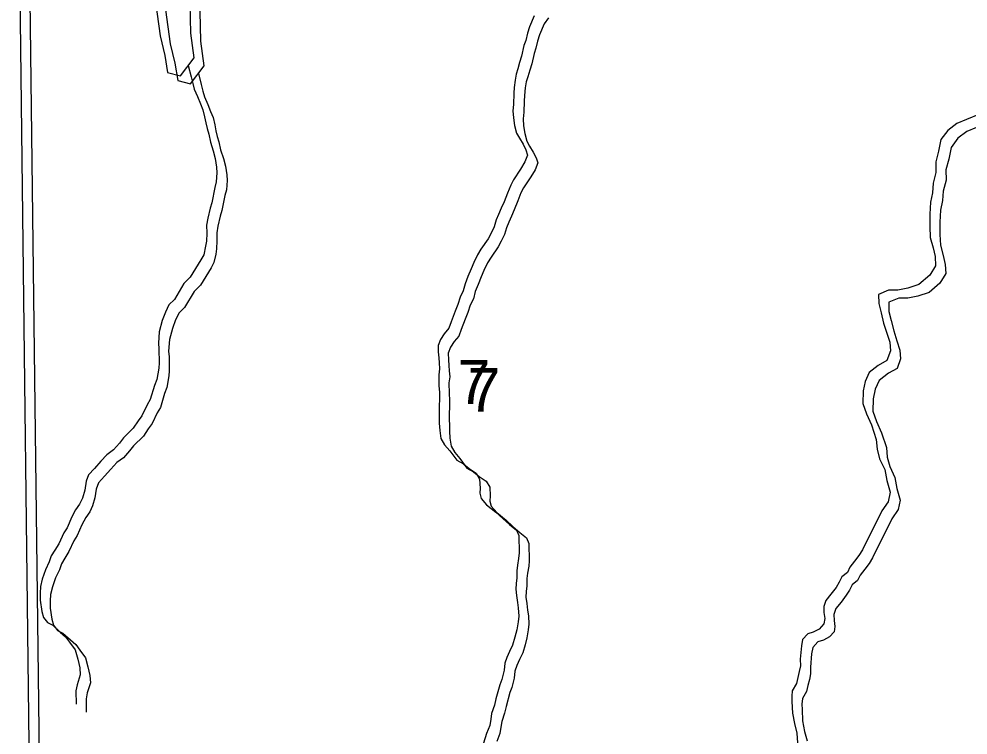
# Model space of a CAD drawing. Extents: x -21.1 to 50.3, y -4.9 to 22.1.
# Drawn here: x 44.094 to 44.997, y 17.935 to 18.617 of the extents above; entities that cross this region are included whole.
import ezdxf

# ---------------------------------------------------------------- set-up
doc = ezdxf.new("R2010")
doc.units = 0
for name, color, linetype in [('GM_X_Minor_Lake', 7, 'Continuous'), ('GM_X_Minor_River', 7, 'Continuous'), ('GM_X_Section', 7, 'Continuous'), ('GM_X_Section_Text', 7, 'Continuous')]:
    doc.layers.add(name, color=color, linetype=linetype)

msp = doc.modelspace()

# ---------------------------------------------------------------- linework, layer by layer
at = {"layer": 'GM_X_Minor_Lake'}
for points in [[(44.21461, 18.65156), (44.21467, 18.64283), (44.22347, 18.63265), (44.22789, 18.60043), (44.2322, 18.58186), (44.23497, 18.56556), (44.24714, 18.56224), (44.26028, 18.57943), (44.25707, 18.60294), (44.25649, 18.63102), (44.25901, 18.64812), (44.25517, 18.6553), (44.24947, 18.65564)], [(44.22425, 18.64406), (44.22431, 18.63533), (44.23311, 18.62515), (44.23752, 18.59293), (44.24183, 18.57436), (44.24461, 18.55806), (44.25677, 18.55474), (44.26992, 18.57193), (44.26671, 18.59544), (44.26612, 18.62352), (44.26865, 18.64062), (44.2648, 18.6478), (44.25911, 18.64814)]]:
    msp.add_lwpolyline(points, dxfattribs=at)
at = {"layer": 'GM_X_Minor_River'}
for points in [[(44.58378, 18.61937), (44.5793, 18.60907), (44.57745, 18.60297), (44.57599, 18.59612), (44.57413, 18.59116), (44.57193, 18.58125), (44.57008, 18.57516), (44.56823, 18.56905), (44.56675, 18.5641), (44.56566, 18.55839), (44.56496, 18.55116), (44.56463, 18.54583), (44.56434, 18.53518), (44.56363, 18.52909), (44.56407, 18.52225), (44.56527, 18.51504), (44.56723, 18.50783), (44.56993, 18.50291), (44.57341, 18.49723), (44.57611, 18.49193), (44.57767, 18.487), (44.57507, 18.48051), (44.57094, 18.47363), (44.56419, 18.46331), (44.56157, 18.45835), (44.55859, 18.45072), (44.55524, 18.44232), (44.55263, 18.43622), (44.55002, 18.43049), (44.54778, 18.42515), (44.54593, 18.41867), (44.54294, 18.41256), (44.53995, 18.40722), (44.53319, 18.39727), (44.52981, 18.39192), (44.52645, 18.38467)], [(44.59755, 18.61761), (44.59341, 18.61187), (44.58894, 18.60157), (44.58709, 18.59547), (44.58563, 18.58861), (44.58377, 18.58366), (44.58157, 18.57375), (44.57972, 18.56765), (44.57787, 18.56155), (44.57639, 18.5566), (44.5753, 18.55089), (44.5746, 18.54366), (44.57426, 18.53833), (44.57398, 18.52768), (44.57327, 18.52159), (44.5737, 18.51475), (44.57491, 18.50754), (44.57687, 18.50032), (44.57957, 18.4954), (44.58304, 18.48973), (44.58575, 18.48443), (44.58731, 18.4795), (44.58471, 18.47301), (44.58058, 18.46613), (44.57382, 18.45581), (44.5712, 18.45085), (44.56823, 18.44322), (44.56488, 18.43482), (44.56227, 18.42872), (44.55965, 18.42299), (44.55742, 18.41765), (44.55557, 18.41117), (44.55258, 18.40506), (44.54958, 18.39971), (44.54282, 18.38977), (44.53945, 18.38442), (44.53609, 18.37717)], [(44.25467, 18.57209), (44.25727, 18.56158), (44.25884, 18.55513), (44.26041, 18.54982), (44.26351, 18.54262), (44.26623, 18.5358), (44.26856, 18.53011), (44.27014, 18.52328), (44.27133, 18.51759), (44.27251, 18.51227), (44.27408, 18.50696), (44.27566, 18.49937), (44.2784, 18.49103), (44.28036, 18.48382), (44.28157, 18.47546)], [(44.2643, 18.56459), (44.2669, 18.55408), (44.26848, 18.54763), (44.27004, 18.54232), (44.27315, 18.53512), (44.27587, 18.5283), (44.2782, 18.52261), (44.27978, 18.51578), (44.28096, 18.51009), (44.28215, 18.50477), (44.28371, 18.49946), (44.2853, 18.49187), (44.28803, 18.48353), (44.29, 18.47632), (44.29121, 18.46796)], [(45.00787, 18.52577), (44.99534, 18.52077), (44.98623, 18.51691), (44.97751, 18.51041), (44.97109, 18.50164), (44.96887, 18.49061), (44.96626, 18.48034), (44.96631, 18.47046), (44.96371, 18.46019), (44.963, 18.45107), (44.96115, 18.44194), (44.96045, 18.43054), (44.96052, 18.41876), (44.96095, 18.40851), (44.96367, 18.39865), (44.96562, 18.3903), (44.96605, 18.38157), (44.96039, 18.37242), (44.95017, 18.36362), (44.93953, 18.36015), (44.93002, 18.35819), (44.92127, 18.35814), (44.91178, 18.35429), (44.91182, 18.34555), (44.91416, 18.33683), (44.9165, 18.32697), (44.9196, 18.31749), (44.92231, 18.30877), (44.92312, 18.30041), (44.91974, 18.29128), (44.91139, 18.28667), (44.90268, 18.27978), (44.89892, 18.27141), (44.89707, 18.26228), (44.89675, 18.2505), (44.90023, 18.24064), (44.90486, 18.23003), (44.90951, 18.216), (44.91032, 18.20689), (44.91266, 18.19779), (44.91766, 18.18756), (44.91963, 18.17693), (44.92273, 18.16593), (44.92088, 18.1568), (44.91484, 18.14803), (44.89634, 18.11105)], [(45.00498, 18.51326), (44.99586, 18.50941), (44.98714, 18.50291), (44.98072, 18.49414), (44.9785, 18.48311), (44.97589, 18.47283), (44.97595, 18.46296), (44.97334, 18.45269), (44.97263, 18.44357), (44.97078, 18.43444), (44.97008, 18.42304), (44.97015, 18.41126), (44.97059, 18.40101), (44.97331, 18.39115), (44.97526, 18.3828), (44.97569, 18.37407), (44.97003, 18.36492), (44.9598, 18.35612), (44.94917, 18.35264), (44.93966, 18.35069), (44.93091, 18.35064), (44.92141, 18.34679), (44.92146, 18.33805), (44.92379, 18.32933), (44.92613, 18.31946), (44.92923, 18.30999), (44.93195, 18.30126), (44.93275, 18.29291), (44.92938, 18.28378), (44.92103, 18.27917), (44.91231, 18.27228), (44.90856, 18.26391), (44.9067, 18.25478), (44.90639, 18.243), (44.90987, 18.23314), (44.9145, 18.22253), (44.91914, 18.2085), (44.91996, 18.19939), (44.92229, 18.19029), (44.9273, 18.18006), (44.92926, 18.16943), (44.93237, 18.15843), (44.93052, 18.1493), (44.92448, 18.14053), (44.90597, 18.10355)], [(44.28157, 18.47546), (44.28199, 18.47014), (44.28131, 18.46139), (44.27983, 18.45605), (44.27692, 18.44158), (44.27544, 18.43624), (44.27324, 18.42672), (44.27215, 18.42025), (44.27222, 18.41264), (44.2719, 18.40504), (44.27118, 18.40009), (44.26935, 18.39209), (44.26673, 18.38712), (44.2566, 18.37069), (44.25057, 18.36455), (44.24157, 18.34927), (44.23629, 18.34428), (44.23293, 18.33741), (44.22995, 18.3294), (44.227, 18.31873), (44.22634, 18.3077), (44.22676, 18.30238), (44.22688, 18.28907), (44.22654, 18.28412), (44.22473, 18.27308), (44.2225, 18.26736), (44.21843, 18.25402), (44.21543, 18.24905), (44.21057, 18.23874), (44.20681, 18.23377), (44.20231, 18.22689), (44.19288, 18.21769), (44.18912, 18.21271), (44.18347, 18.2062), (44.17704, 18.20159), (44.17139, 18.19546), (44.16537, 18.18856), (44.15972, 18.18243), (44.15749, 18.17633), (44.15604, 18.16795), (44.15382, 18.16033), (44.15121, 18.15461), (44.14745, 18.14925), (44.14371, 18.14237), (44.13923, 18.13207), (44.13623, 18.1271), (44.13138, 18.1168), (44.12762, 18.11068), (44.12425, 18.10533), (44.12239, 18.09961), (44.11866, 18.09198), (44.11569, 18.08321), (44.11385, 18.07597), (44.11352, 18.06988), (44.11358, 18.06304), (44.11519, 18.0524), (44.11676, 18.04671), (44.1206, 18.0418), (44.12557, 18.03918), (44.13285, 18.03277), (44.13783, 18.02825), (44.14168, 18.02296), (44.14706, 18.01578), (44.14942, 18.00705), (44.15139, 17.9987), (44.15182, 17.99186), (44.14886, 17.98233), (44.14777, 17.97662), (44.14788, 17.96407)], [(44.29121, 18.46796), (44.29163, 18.46264), (44.29095, 18.45389), (44.28947, 18.44855), (44.28655, 18.43408), (44.28508, 18.42874), (44.28287, 18.41922), (44.28179, 18.41275), (44.28185, 18.40514), (44.28154, 18.39754), (44.28082, 18.39258), (44.27899, 18.38458), (44.27637, 18.37962), (44.26624, 18.36319), (44.26021, 18.35705), (44.25121, 18.34177), (44.24593, 18.33678), (44.24257, 18.32991), (44.23959, 18.3219), (44.23664, 18.31123), (44.23597, 18.3002), (44.2364, 18.29488), (44.23651, 18.28157), (44.23617, 18.27662), (44.23437, 18.26558), (44.23213, 18.25986), (44.22806, 18.24652), (44.22506, 18.24155), (44.22021, 18.23124), (44.21645, 18.22627), (44.21194, 18.21939), (44.20252, 18.21018), (44.19876, 18.20521), (44.19311, 18.1987), (44.18668, 18.19409), (44.18103, 18.18796), (44.175, 18.18106), (44.16935, 18.17493), (44.16712, 18.16883), (44.16567, 18.16045), (44.16346, 18.15283), (44.16085, 18.14711), (44.15709, 18.14175), (44.15334, 18.13487), (44.14887, 18.12457), (44.14587, 18.1196), (44.14101, 18.1093), (44.13726, 18.10318), (44.13389, 18.09783), (44.13203, 18.09211), (44.12829, 18.08448), (44.12533, 18.07571), (44.12349, 18.06847), (44.12316, 18.06238), (44.12322, 18.05554), (44.12483, 18.0449), (44.1264, 18.03921), (44.13024, 18.0343), (44.13521, 18.03168), (44.14248, 18.02527), (44.14746, 18.02075), (44.15131, 18.01546), (44.1567, 18.00828), (44.15905, 17.99955), (44.16102, 17.9912), (44.16146, 17.98436), (44.1585, 17.97483), (44.15741, 17.96911), (44.15752, 17.95657)], [(44.52645, 18.38467), (44.52384, 18.37857), (44.52086, 18.37132), (44.51825, 18.36445), (44.51641, 18.35759), (44.51342, 18.35148), (44.5112, 18.34462), (44.50859, 18.33814), (44.50487, 18.32822), (44.50264, 18.32212), (44.49813, 18.31676), (44.49475, 18.31141), (44.49252, 18.30568), (44.49257, 18.2996), (44.493, 18.2939), (44.49342, 18.28896), (44.49385, 18.28326), (44.49314, 18.27755), (44.49322, 18.26728), (44.49365, 18.2612), (44.49371, 18.25436), (44.49338, 18.24827), (44.49353, 18.23154), (44.49396, 18.2247), (44.49517, 18.21711), (44.49864, 18.21105), (44.50363, 18.20539), (44.51017, 18.19631), (44.51667, 18.19295), (44.52203, 18.18842), (44.52853, 18.18391), (44.532, 18.17824), (44.53245, 18.16988), (44.53211, 18.16493), (44.53329, 18.16), (44.53867, 18.15396), (44.54747, 18.1468), (44.55399, 18.14077), (44.5605, 18.13512), (44.56701, 18.12985), (44.56934, 18.12455), (44.56948, 18.1082), (44.56914, 18.10287), (44.56805, 18.0964), (44.56734, 18.09107), (44.5674, 18.08422), (44.56668, 18.07889), (44.56635, 18.07357), (44.56716, 18.06749), (44.56797, 18.06103), (44.56878, 18.05571), (44.56923, 18.04773), (44.56851, 18.0424), (44.56743, 18.03479), (44.56559, 18.02793), (44.56338, 18.02031), (44.56038, 18.0142), (44.55777, 18.00847), (44.55592, 18.00313), (44.55521, 17.99628), (44.55301, 17.98752), (44.55115, 17.98256), (44.54746, 17.96922), (44.54599, 17.96312), (44.54339, 17.95512), (44.54268, 17.94979), (44.54159, 17.9437), (44.53861, 17.93607), (44.53565, 17.92692)], [(44.53609, 18.37717), (44.53348, 18.37107), (44.5305, 18.36382), (44.52789, 18.35695), (44.52605, 18.35009), (44.52306, 18.34398), (44.52083, 18.33712), (44.51823, 18.33064), (44.51451, 18.32072), (44.51228, 18.31461), (44.50776, 18.30925), (44.50439, 18.3039), (44.50215, 18.29818), (44.50221, 18.2921), (44.50263, 18.2864), (44.50306, 18.28146), (44.50349, 18.27576), (44.50277, 18.27005), (44.50286, 18.25978), (44.50329, 18.2537), (44.50335, 18.24686), (44.50302, 18.24077), (44.50316, 18.22404), (44.5036, 18.2172), (44.5048, 18.20961), (44.50828, 18.20355), (44.51327, 18.19789), (44.51981, 18.18881), (44.5263, 18.18544), (44.53166, 18.18092), (44.53817, 18.17641), (44.54164, 18.17074), (44.54209, 18.16238), (44.54175, 18.15743), (44.54293, 18.1525), (44.54831, 18.14646), (44.55711, 18.1393), (44.56363, 18.13327), (44.57014, 18.12762), (44.57665, 18.12235), (44.57897, 18.11704), (44.57911, 18.10069), (44.57878, 18.09537), (44.57769, 18.0889), (44.57697, 18.08357), (44.57703, 18.07672), (44.57632, 18.07139), (44.57598, 18.06607), (44.57679, 18.05999), (44.57761, 18.05353), (44.57841, 18.04821), (44.57886, 18.04023), (44.57815, 18.0349), (44.57707, 18.02729), (44.57523, 18.02043), (44.57301, 18.01281), (44.57002, 18.0067), (44.56741, 18.00097), (44.56555, 17.99563), (44.56485, 17.98878), (44.56264, 17.98002), (44.56078, 17.97506), (44.55709, 17.96172), (44.55562, 17.95562), (44.55303, 17.94762), (44.55232, 17.94229), (44.55123, 17.9362), (44.54825, 17.92857)], [(44.89634, 18.11105), (44.89307, 18.10551), (44.88894, 18.10015), (44.88442, 18.09441), (44.88218, 18.08945), (44.87689, 18.08522), (44.87428, 18.08026), (44.87128, 18.07529), (44.86639, 18.06878), (44.8615, 18.06266), (44.85964, 18.05694), (44.85969, 18.05124), (44.8605, 18.04554), (44.85978, 18.04059), (44.85526, 18.03561), (44.84958, 18.03252), (44.84427, 18.03096), (44.83938, 18.02559), (44.83829, 18.0195), (44.83725, 18.00695), (44.83731, 18.00048), (44.83621, 17.99515), (44.83474, 17.98943), (44.83365, 17.98372), (44.82952, 17.97684), (44.82919, 17.97152), (44.82923, 17.96657), (44.8297, 17.95555), (44.83169, 17.94568), (44.83405, 17.93657), (44.83492, 17.92289)], [(44.90597, 18.10355), (44.90271, 18.098), (44.89857, 18.09265), (44.89406, 18.08691), (44.89182, 18.08195), (44.88653, 18.07772), (44.88391, 18.07275), (44.88091, 18.06779), (44.87603, 18.06128), (44.87113, 18.05516), (44.86928, 18.04944), (44.86933, 18.04374), (44.87014, 18.03804), (44.86942, 18.03309), (44.8649, 18.02811), (44.85922, 18.02502), (44.85391, 18.02346), (44.84901, 18.01809), (44.84793, 18.012), (44.84689, 17.99944), (44.84694, 17.99298), (44.84585, 17.98765), (44.84438, 17.98193), (44.84328, 17.97622), (44.83916, 17.96934), (44.83882, 17.96402), (44.83887, 17.95907), (44.83934, 17.94805), (44.84132, 17.93818), (44.84368, 17.92907)]]:
    msp.add_lwpolyline(points, dxfattribs=at)
at = {"layer": 'GM_X_Section'}
for points in [[(44.0935, 18.71999), (45.13143, 18.72623), (45.14863, 17.70187), (44.10665, 17.68876), (44.1055, 17.74068), (44.09428, 18.66845)], [(44.10314, 18.71249), (45.14107, 18.71873), (45.15827, 17.69437), (44.11629, 17.68126), (44.11514, 17.73318), (44.10391, 18.66095)]]:
    msp.add_lwpolyline(points, close=True, dxfattribs=at)

# ---------------------------------------------------------------- texts
at = {"layer": 'GM_X_Section_Text'}
for p in [(44.51092, 18.24995), (44.52056, 18.24245)]:
    msp.add_text('7', height=0.04186, rotation=0.00001, dxfattribs=at).set_placement(p)

doc.saveas('drawing.dxf')
